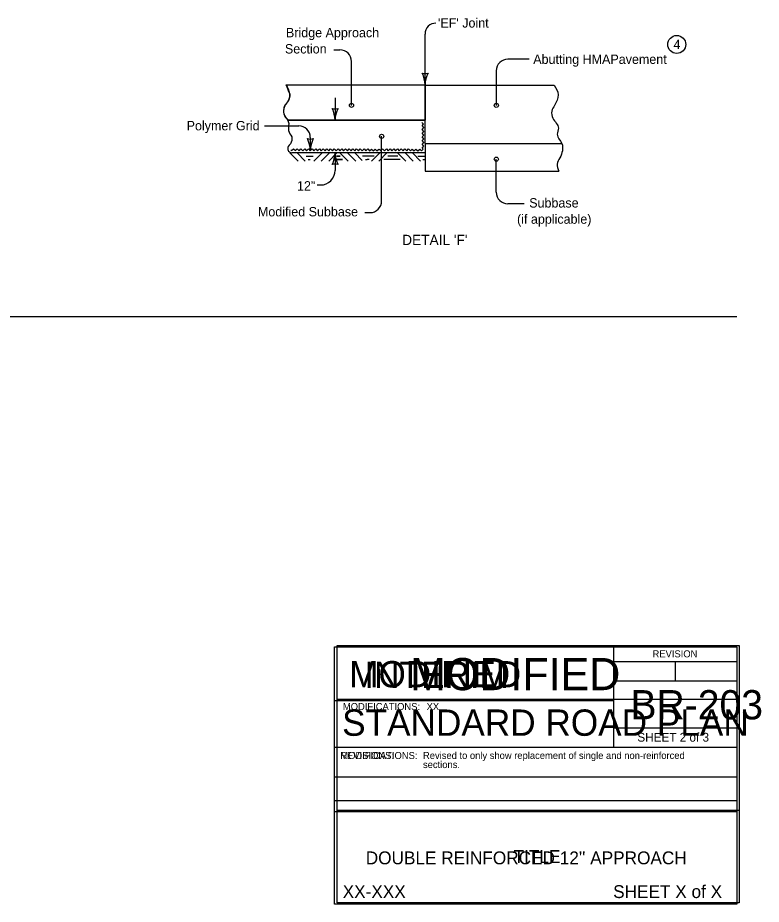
# Model space of a CAD drawing. Extents: x -2134860 to -2124557, y -2139046 to -2137324.
# Drawn here: x -2129429 to -2128157, y -2139046 to -2137530 of the extents above; entities that cross this region are included whole.
import ezdxf

# ---------------------------------------------------------------- set-up
doc = ezdxf.new("R2010")
doc.units = 0
for name, color, linetype in [('BridgeSuperStructureExisting', 7, 'Continuous'), ('Dimension', 7, 'Continuous'), ('dsnAlignmentCurveData', 7, 'Continuous'), ('dsnAlignmentTic', 7, 'Continuous'), ('DsnShtInsideBorder', 7, 'Continuous'), ('DsnShtPlotIdentification', 7, 'Continuous'), ('dsnStdLabel', 7, 'Continuous'), ('TC_Barrier', 7, 'Continuous')]:
    doc.layers.add(name, color=color, linetype=linetype)

msp = doc.modelspace()

# ---------------------------------------------------------------- linework, layer by layer
at = {"layer": 'BridgeSuperStructureExisting'}
for p, q in [((-2128732.5, -2137644.8), (-2128732.5, -2137558)), ((-2128888.8, -2137585.1), (-2128878.2, -2137585.1)), ((-2128858.4, -2137680), (-2128858.4, -2137604.9)), ((-2128554.4, -2137600.9), (-2128590.9, -2137600.9)), ((-2128610.7, -2137620.7), (-2128610.7, -2137680)), ((-2128732.5, -2137645.4), (-2128970.5, -2137645.4)), ((-2128732.5, -2137645.4), (-2128970.2, -2137645.4)), ((-2128732.5, -2137705.4), (-2128732.5, -2137645.4)), ((-2128732.5, -2137645.4), (-2128511.5, -2137645.4)), ((-2128732.5, -2137645.4), (-2128732.5, -2137705.4)), ((-2128886.6, -2137667), (-2128886.6, -2137705.4)), ((-2129007.2, -2137714.9), (-2128948.7, -2137714.9)), ((-2128967.4, -2137705.4), (-2128732.5, -2137705.4)), ((-2128732.5, -2137705.4), (-2128967.4, -2137705.4)), ((-2128732.5, -2137745.4), (-2128732.5, -2137705.4)), ((-2128806.9, -2137843.5), (-2128806.9, -2137732.9)), ((-2128732.9, -2137733.8), (-2128732.9, -2137733.8)), ((-2128928.9, -2137734.7), (-2128928.9, -2137757)), ((-2128732.5, -2137745.4), (-2128498.7, -2137745.4)), ((-2128732.5, -2137745.4), (-2128732.5, -2137792.6)), ((-2128963.8, -2137761.4), (-2128949.8, -2137775.4)), ((-2128732.9, -2137761.2), (-2128960.5, -2137761.2)), ((-2128930, -2137761.2), (-2128958.4, -2137761.2)), ((-2128951.4, -2137761.2), (-2128937.4, -2137775.2)), ((-2128930, -2137761.2), (-2128930, -2137761.2)), ((-2128831.5, -2137761.2), (-2128930, -2137761.2)), ((-2128930, -2137761.2), (-2128930, -2137761.2)), ((-2128908.6, -2137761.2), (-2128922.6, -2137775.2)), ((-2128896.3, -2137761.4), (-2128910.3, -2137775.4)), ((-2128883.4, -2137761.2), (-2128897.4, -2137775.2)), ((-2128886.6, -2137761), (-2128886.6, -2137791.1)), ((-2128878.1, -2137761.2), (-2128864.1, -2137775.2)), ((-2128865.2, -2137761.4), (-2128851.2, -2137775.4)), ((-2128852.9, -2137761.2), (-2128840, -2137774.1)), ((-2128831.5, -2137761.2), (-2128831.5, -2137761.2)), ((-2128732.9, -2137761.2), (-2128831.5, -2137761.2)), ((-2128831.5, -2137761.2), (-2128831.5, -2137761.2)), ((-2128810.1, -2137761.2), (-2128824.1, -2137775.2)), ((-2128797.8, -2137761.4), (-2128811.8, -2137775.4)), ((-2128779.5, -2137761.2), (-2128765.5, -2137775.2)), ((-2128766.7, -2137761.4), (-2128752.7, -2137775.4)), ((-2128754.3, -2137761.2), (-2128740.3, -2137775.2)), ((-2128924, -2137767.4), (-2128935.9, -2137767.4)), ((-2128932.4, -2137772.4), (-2128929.1, -2137772.4)), ((-2128887.8, -2137772.5), (-2128873.7, -2137772.5)), ((-2128887.8, -2137772.5), (-2128873.7, -2137772.5)), ((-2128873.7, -2137772.5), (-2128887.8, -2137772.5)), ((-2128873.7, -2137772.5), (-2128887.8, -2137772.5)), ((-2128884, -2137766.7), (-2128877.5, -2137766.7)), ((-2128884, -2137766.7), (-2128877.5, -2137766.7)), ((-2128877.5, -2137766.7), (-2128884, -2137766.7)), ((-2128877.5, -2137766.7), (-2128884, -2137766.7)), ((-2128819.6, -2137766.6), (-2128839.8, -2137766.6)), ((-2128834.7, -2137772.4), (-2128831.5, -2137772.4)), ((-2128828.3, -2137772.4), (-2128831.5, -2137772.4)), ((-2128828.3, -2137772.4), (-2128828.3, -2137772.4)), ((-2128822.5, -2137766.6), (-2128822.5, -2137766.6)), ((-2128775.2, -2137772.5), (-2128803, -2137772.5)), ((-2128779, -2137766.7), (-2128796.1, -2137766.7)), ((-2128779, -2137766.7), (-2128783.9, -2137766.7)), ((-2128744.8, -2137766.6), (-2128732.9, -2137766.6)), ((-2128741.9, -2137766.6), (-2128741.9, -2137766.6)), ((-2128736.2, -2137772.4), (-2128736.2, -2137772.4)), ((-2128736.2, -2137772.4), (-2128732.9, -2137772.4)), ((-2128610.7, -2137828.5), (-2128610.7, -2137772)), ((-2128732.5, -2137792.6), (-2128503.6, -2137792.6)), ((-2128917.2, -2137816.1), (-2128911.6, -2137816.1)), ((-2128562.9, -2137848.3), (-2128590.9, -2137848.3)), ((-2128835.8, -2137863.3), (-2128826.7, -2137863.3))]:
    msp.add_line(p, q, dxfattribs=at)
for points in [[(-2128735.2, -2137712), (-2128737.8, -2137709.3)], [(-2128735.7, -2137754.8), (-2128737.6, -2137752.9), (-2128734.4, -2137749.8), (-2128737.6, -2137746.6), (-2128734.4, -2137743.4), (-2128737.6, -2137740.2), (-2128734.4, -2137737.1), (-2128737.6, -2137733.9), (-2128734.4, -2137730.7), (-2128737.6, -2137727.6), (-2128734.4, -2137724.4), (-2128737.5, -2137721.2), (-2128734.4, -2137718.1), (-2128737.5, -2137714.9), (-2128735.2, -2137712)], [(-2128962.3, -2137755.8), (-2128960.7, -2137757.4), (-2128957.6, -2137754.3), (-2128954.4, -2137757.4), (-2128951.2, -2137754.3), (-2128948.1, -2137757.5), (-2128944.9, -2137754.3), (-2128941.7, -2137757.5), (-2128938.5, -2137754.3), (-2128935.4, -2137757.5), (-2128932.2, -2137754.3), (-2128929, -2137757.5), (-2128925.9, -2137754.4), (-2128922.7, -2137757.5), (-2128919.5, -2137754.4), (-2128916.4, -2137757.5), (-2128913.2, -2137754.4), (-2128910, -2137757.6), (-2128906.9, -2137754.4), (-2128903.7, -2137757.6), (-2128900.5, -2137754.4), (-2128897.4, -2137757.6), (-2128894.2, -2137754.4), (-2128891, -2137757.6), (-2128887.9, -2137754.5), (-2128886.4, -2137755.6)], [(-2128886.1, -2137756), (-2128884.5, -2137757.6), (-2128881.3, -2137754.4), (-2128878.2, -2137757.6), (-2128875, -2137754.4), (-2128871.8, -2137757.6), (-2128868.7, -2137754.4), (-2128865.5, -2137757.6), (-2128862.3, -2137754.5), (-2128859.2, -2137757.6), (-2128856, -2137754.5), (-2128852.8, -2137757.6), (-2128849.7, -2137754.5), (-2128846.5, -2137757.7), (-2128843.3, -2137754.5), (-2128840.2, -2137757.7), (-2128837, -2137754.5), (-2128833.8, -2137757.7), (-2128830.7, -2137754.5), (-2128827.5, -2137757.7), (-2128824.3, -2137754.6), (-2128821.2, -2137757.7), (-2128818, -2137754.6), (-2128814.8, -2137757.7), (-2128811.6, -2137754.6), (-2128810.2, -2137755.7)], [(-2128809.8, -2137756), (-2128808.3, -2137757.6), (-2128805.1, -2137754.4), (-2128801.9, -2137757.6), (-2128798.7, -2137754.4), (-2128795.6, -2137757.6), (-2128792.4, -2137754.5), (-2128789.2, -2137757.6), (-2128786.1, -2137754.5), (-2128782.9, -2137757.7), (-2128779.7, -2137754.5), (-2128776.6, -2137757.7), (-2128773.4, -2137754.5), (-2128770.2, -2137757.7), (-2128767.1, -2137754.5), (-2128763.9, -2137757.7), (-2128760.7, -2137754.5), (-2128757.6, -2137757.7), (-2128754.4, -2137754.6), (-2128751.2, -2137757.7), (-2128748.1, -2137754.6), (-2128744.9, -2137757.8), (-2128741.7, -2137754.6), (-2128738.6, -2137757.8), (-2128735.7, -2137754.9)]]:
    msp.add_lwpolyline(points, dxfattribs=at)
msp.add_circle((-2128302, -2137575.9), 15.4, dxfattribs=at)
for centre, radius, start, end in [((-2128714, -2137558), 18.6, 90, 180), ((-2128878.2, -2137604.9), 19.8, 0, 90), ((-2128590.9, -2137620.7), 19.8, 90, 180), ((-2128732.5, -2137609), 16.5, 252.2666, 287.7333), ((-2128775.3, -2137644.8), 42.7, 360, 28.0725), ((-2128732.5, -2137609), 16.5, 252.2666, 287.7333), ((-2128775.3, -2137644.8), 42.7, 360, 28.0725), ((-2128689.8, -2137644.8), 42.7, 151.9275, 180), ((-2128689.8, -2137644.8), 42.7, 151.9275, 180), ((-2128886.6, -2137669.5), 16.5, 252.2666, 287.7333), ((-2128929.3, -2137705.4), 42.7, 360, 28.0725), ((-2128843.8, -2137705.4), 42.7, 151.9275, 180), ((-2128948.7, -2137734.7), 19.8, 0, 90), ((-2128928.9, -2137721.1), 16.5, 252.2667, 287.7334), ((-2128971.6, -2137757), 42.7, 0, 28.0725), ((-2128886.1, -2137757), 42.7, 151.9275, 180), ((-2128929.3, -2137761), 42.7, 331.9275, 360), ((-2128843.8, -2137761), 42.7, 180, 208.0725), ((-2128911.6, -2137791.1), 25, 270, 0), ((-2128886.6, -2137796.8), 16.5, 72.2666, 107.7334), ((-2128590.9, -2137828.5), 19.8, 180, 270), ((-2128826.7, -2137843.5), 19.8, 270, 360)]:
    msp.add_arc(centre, radius, start, end, dxfattribs=at)
for points in [[(-2128970.5, -2137644.6), (-2128964.4, -2137659.8), (-2128964.6, -2137666.8), (-2128974.4, -2137686), (-2128972.9, -2137697.4), (-2128966.5, -2137707.5), (-2128965.9, -2137722.9), (-2128960.5, -2137733.8)], [(-2128511.5, -2137645.4), (-2128505, -2137661.7), (-2128511.1, -2137680), (-2128515.7, -2137689.9), (-2128514.1, -2137702), (-2128504.3, -2137718.8), (-2128506.5, -2137729.4), (-2128498.7, -2137745.4), (-2128502, -2137769.7), (-2128506.5, -2137780.4), (-2128503.6, -2137792.7)], [(-2128960.5, -2137733.8), (-2128960.5, -2137740.3), (-2128967, -2137750.5)], [(-2128967, -2137750.5), (-2128967, -2137756.9), (-2128960.5, -2137761.2)]]:
    msp.add_spline(points, degree=3, dxfattribs=at)
msp.add_open_spline([(-2128970.2, -2137645.4), (-2128968.3, -2137650.2), (-2128966.4, -2137655), (-2128964.4, -2137659.8), (-2128963.6, -2137662), (-2128964.1, -2137664.6), (-2128964.6, -2137666.8), (-2128966, -2137673.7), (-2128973.2, -2137679.3), (-2128974.4, -2137686), (-2128975, -2137689.6), (-2128974.3, -2137693.8), (-2128972.9, -2137697.4), (-2128971.8, -2137700.4), (-2128969.1, -2137702.7), (-2128967.4, -2137705.4)], degree=3, dxfattribs=at)
at = {"layer": 'Dimension'}
for p, q in [((-2128410.4, -2138605.9), (-2128410.4, -2138697.3)), ((-2128410.4, -2138630.9), (-2128199.4, -2138630.9)), ((-2128304.9, -2138630.9), (-2128304.9, -2138664.1)), ((-2128410.4, -2138664.1), (-2128199.4, -2138664.1)), ((-2128887.5, -2138697.3), (-2128410.4, -2138697.3)), ((-2128410.4, -2138697.3), (-2128410.4, -2138777.3)), ((-2128199.4, -2138745.1), (-2128410.4, -2138745.1)), ((-2128887.5, -2138777.3), (-2128199.4, -2138777.3)), ((-2128887.5, -2138828.3), (-2128199.4, -2138828.3)), ((-2128887.5, -2138868.3), (-2128199.4, -2138868.3)), ((-2128887.5, -2138887.3), (-2128199.4, -2138887.3))]:
    msp.add_line(p, q, dxfattribs=at)
msp.add_lwpolyline([(-2128887.5, -2138605.9), (-2128199.4, -2138605.9), (-2128199.4, -2139045.9), (-2128887.5, -2139045.9)], close=True, dxfattribs=at)
msp.add_lwpolyline([(-2128887.5, -2138605.9), (-2128199.4, -2138605.9), (-2128199.4, -2139045.9), (-2128887.5, -2139045.9)], close=True, dxfattribs=at)
at = {"layer": 'dsnAlignmentCurveData'}
msp.add_line((-2131334.4, -2138040.9), (-2128199.4, -2138040.9), dxfattribs=at)
at = {"layer": 'DsnShtInsideBorder'}
for p, q in [((-2128883.1, -2138695), (-2128195.1, -2138695)), ((-2128883.1, -2138885), (-2128195.1, -2138885))]:
    msp.add_line(p, q, dxfattribs=at)
msp.add_lwpolyline([(-2128883.1, -2138603.7), (-2128195.1, -2138603.7), (-2128195.1, -2139043.7), (-2128883.1, -2139043.7)], close=True, dxfattribs=at)
at = {"layer": 'TC_Barrier'}
for centre in [(-2128858.4, -2137680), (-2128610.7, -2137680), (-2128806.9, -2137732.9), (-2128610.7, -2137772)]:
    msp.add_circle(centre, 3.54, dxfattribs=at)

# ---------------------------------------------------------------- texts
at = {"layer": 'BridgeSuperStructureExisting'}
msp.add_text("DETAIL 'F'", height=17.5, dxfattribs=at).set_placement((-2128771.7, -2137918.8))
at = {"layer": 'Dimension'}
for s, height, p in [('REVISION', 12, (-2128343.4, -2138623.8)), ('BR-203', 50, (-2128381.2, -2138729.8)), ('STANDARD ROAD PLAN', 45.001, (-2128874.4, -2138757.9)), ('SHEET 2 of 3', 15, (-2128369.4, -2138767.9)), ('Revised to only show replacement of single and non-reinforced', 12, (-2128736.1, -2138797.5)), ('sections.', 12, (-2128736.1, -2138813.1)), ("DOUBLE REINFORCED 12'' APPROACH", 22, (-2128834, -2138977.6))]:
    msp.add_text(s, height=height, dxfattribs=at).set_placement(p)
at = {"layer": 'dsnAlignmentCurveData'}
msp.add_text('REVISIONS:', height=12, dxfattribs=at).set_placement((-2128877.5, -2138797.6))
at = {"layer": 'dsnAlignmentTic'}
for s, height, p in [('MODIFIED', 45, (-2128862.4, -2138675.1)), ('MODIFICATIONS:', 12, (-2128877.5, -2138797.6))]:
    msp.add_text(s, height=height, dxfattribs=at).set_placement(p)
at = {"layer": 'DsnShtInsideBorder'}
for s, height, p in [('MODIFIED', 55, (-2128758.1, -2138679.9)), ('MODIFICATIONS:', 12, (-2128873.1, -2138713.9)), ('XX', 12, (-2128729.9, -2138713.9)), ('TITLE', 22, (-2128581.1, -2138975.4)), ('XX-XXX', 22, (-2128873.5, -2139035.3)), ('SHEET X of X', 22, (-2128410.8, -2139035.3))]:
    msp.add_text(s, height=height, dxfattribs=at).set_placement(p)
at = {"layer": 'DsnShtPlotIdentification'}
msp.add_text('INTERIM', height=45, dxfattribs=at).set_placement((-2128836.5, -2138676.3))
at = {"layer": 'dsnStdLabel'}
for s, p in [("'EF' Joint", (-2128710.4, -2137547)), ('Bridge Approach', (-2128970.5, -2137563.6)), ('Section', (-2128972.3, -2137591.3)), ('4', (-2128307.6, -2137583.9)), ('Abutting HMAPavement', (-2128547.5, -2137609.1)), ('Polymer Grid', (-2129140.4, -2137722.7)), ('12"', (-2128951.6, -2137825.6)), ('Subbase', (-2128554.4, -2137854.7)), ('Modified Subbase', (-2129018.5, -2137869.8)), ('(if applicable)', (-2128575.2, -2137882.4))]:
    msp.add_text(s, height=16, dxfattribs=at).set_placement(p)

doc.saveas('drawing.dxf')
